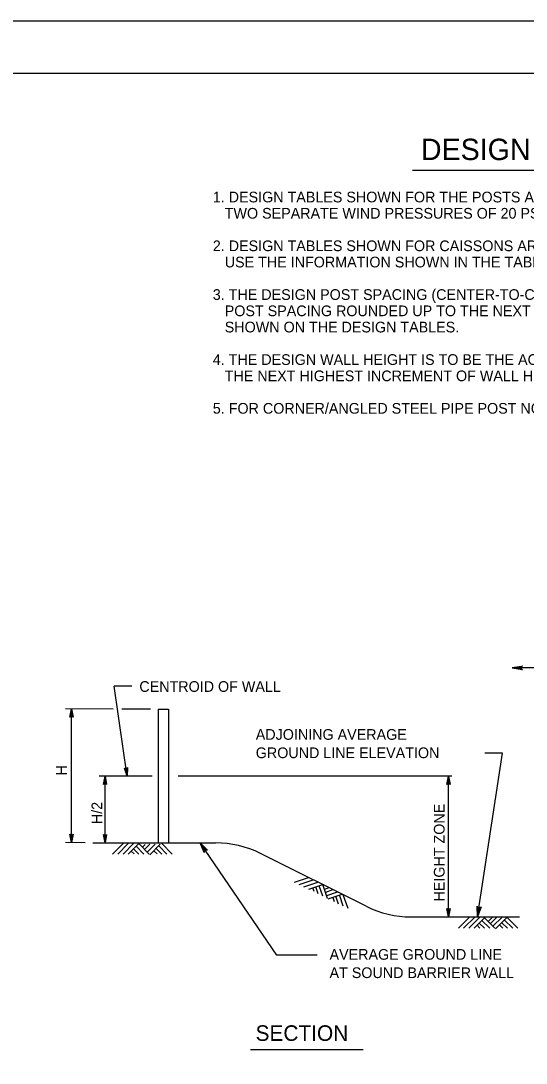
# Model space of a CAD drawing. Extents: x 3475 to 6558, y -3780 to 1166.
# Drawn here: x 4085.3 to 4230.4, y 866.1 to 1165.7 of the extents above; entities that cross this region are included whole.
import ezdxf

# ---------------------------------------------------------------- set-up
doc = ezdxf.new("R2010")
doc.units = 0
for name, color, linetype in [('1', 7, 'Continuous'), ('2', 7, 'Continuous'), ('PLT-BNDY', 7, 'Continuous')]:
    doc.layers.add(name, color=color, linetype=linetype)

msp = doc.modelspace()

# ---------------------------------------------------------------- linework, layer by layer
at = {"layer": '1'}
for p, q in [((4197.8, 1122.78), (4311.11, 1122.78)), ((4363.67, 979.68), (4226.38, 979.68)), ((4117.22, 974.43), (4112.14, 974.43)), ((4115.85, 948.61), (4112.14, 974.43)), ((4111.83, 967.81), (4098.18, 967.92)), ((4099.87, 929.52), (4099.87, 967.92)), ((4122.61, 967.81), (4114.29, 967.81)), ((4124.78, 967.81), (4127.78, 967.81)), ((4124.78, 967.81), (4124.78, 929.41)), ((4127.78, 967.81), (4127.78, 929.41)), ((4216.51, 908.13), (4223.67, 955.16)), ((4223.67, 955.16), (4218.59, 955.16)), ((4123.07, 948.61), (4107.83, 948.61)), ((4109.52, 929.41), (4109.52, 948.61)), ((4209.08, 948.61), (4130.53, 948.61)), ((4208.13, 908.13), (4208.13, 948.61)), ((4103.83, 929.41), (4098.18, 929.52)), ((4105.99, 929.41), (4141.25, 929.41)), ((4111.69, 926.18), (4114.69, 929.18)), ((4113.19, 926.18), (4116.19, 929.18)), ((4114.69, 926.18), (4117.69, 929.18)), ((4116.19, 926.18), (4119.19, 929.18)), ((4122.19, 926.18), (4119.19, 929.18)), ((4121.04, 928.94), (4120.22, 928.12)), ((4122.37, 929), (4120.87, 927.5)), ((4123.87, 929), (4121.62, 926.75)), ((4125.37, 929), (4122.37, 926)), ((4128.78, 926.18), (4125.78, 929.18)), ((4158.88, 897.11), (4136.78, 929.41)), ((4117.87, 926.23), (4117.04, 927.06)), ((4119.19, 926.18), (4117.69, 927.68)), ((4120.69, 926.18), (4118.44, 928.43)), ((4124.46, 926.23), (4123.63, 927.06)), ((4125.78, 926.18), (4124.28, 927.68)), ((4127.28, 926.18), (4125.03, 928.43)), ((4184.53, 911.17), (4154.13, 926.37)), ((4163.95, 918.06), (4167.97, 919.42)), ((4165.3, 917.4), (4169.32, 918.76)), ((4166.64, 916.73), (4170.66, 918.1)), ((4167.99, 916.07), (4172.01, 917.43)), ((4172.02, 914.08), (4171, 917.09)), ((4173.37, 913.41), (4172.01, 917.43)), ((4169.52, 915.38), (4169.14, 916.48)), ((4170.68, 914.74), (4170, 916.75)), ((4173.56, 916.4), (4172.46, 916.03)), ((4174.78, 915.86), (4172.77, 915.18)), ((4176.12, 915.2), (4173.11, 914.18)), ((4177.47, 914.54), (4173.45, 913.18)), ((4176.59, 911.82), (4175.9, 913.83)), ((4177.93, 911.16), (4176.91, 914.17)), ((4179.28, 910.49), (4177.91, 914.51)), ((4175.42, 912.46), (4175.05, 913.56)), ((4197.41, 908.13), (4228.51, 908.13)), ((4210.98, 904.84), (4214.26, 908.13)), ((4212.48, 904.84), (4215.76, 908.13)), ((4213.98, 904.84), (4217.26, 908.13)), ((4215.48, 904.84), (4218.76, 908.13)), ((4221.48, 904.84), (4218.48, 907.84)), ((4220.85, 908.13), (4219.51, 906.78)), ((4222.12, 908.13), (4220.15, 906.16)), ((4223.62, 908.13), (4220.9, 905.41)), ((4225.12, 908.13), (4221.65, 904.66)), ((4228.07, 904.84), (4224.95, 907.96)), ((4217.15, 904.9), (4216.34, 905.71)), ((4218.48, 904.84), (4216.98, 906.34)), ((4219.98, 904.84), (4217.73, 907.09)), ((4223.74, 904.9), (4222.82, 905.83)), ((4225.07, 904.84), (4223.45, 906.46)), ((4226.57, 904.84), (4224.2, 907.21)), ((4170.47, 897.11), (4158.88, 897.11)), ((4151.25, 869.97), (4183.67, 869.97))]:
    msp.add_line(p, q, dxfattribs=at)
for points in [[(4226.38, 979.68), (4229.36, 980.24), (4229.25, 980.16), (4229.13, 980.08), (4229.07, 979.98), (4229.01, 979.88), (4229, 979.78), (4228.98, 979.68), (4229, 979.58), (4229.01, 979.48), (4229.07, 979.38), (4229.13, 979.28), (4229.25, 979.2), (4229.36, 979.12), (4226.38, 979.68), (4229.25, 979.2), (4229.13, 979.28), (4226.38, 979.68), (4229.07, 979.38), (4229.01, 979.48), (4226.38, 979.68), (4229, 979.58), (4228.98, 979.68), (4226.38, 979.68), (4229, 979.78), (4229.01, 979.88), (4226.38, 979.68), (4229.07, 979.98), (4229.13, 980.08), (4226.38, 979.68), (4229.25, 980.16)], [(4099.87, 967.92), (4100.32, 965.53), (4100.26, 965.63), (4100.19, 965.72), (4100.11, 965.77), (4100.03, 965.81), (4099.95, 965.83), (4099.87, 965.84), (4099.79, 965.83), (4099.71, 965.81), (4099.63, 965.77), (4099.55, 965.72), (4099.49, 965.63), (4099.43, 965.53), (4099.87, 967.92), (4099.49, 965.63), (4099.55, 965.72), (4099.87, 967.92), (4099.63, 965.77), (4099.71, 965.81), (4099.87, 967.92), (4099.79, 965.83), (4099.87, 965.84), (4099.87, 967.92), (4099.95, 965.83), (4100.03, 965.81), (4099.87, 967.92), (4100.11, 965.77), (4100.19, 965.72), (4099.87, 967.92), (4100.26, 965.63)], [(4115.85, 948.61), (4115.07, 950.91), (4115.14, 950.83), (4115.22, 950.74), (4115.3, 950.71), (4115.39, 950.67), (4115.47, 950.67), (4115.55, 950.67), (4115.63, 950.69), (4115.71, 950.72), (4115.78, 950.78), (4115.85, 950.83), (4115.9, 950.93), (4115.95, 951.03), (4115.85, 948.61), (4115.9, 950.93), (4115.85, 950.83), (4115.85, 948.61), (4115.78, 950.78), (4115.71, 950.72), (4115.85, 948.61), (4115.63, 950.69), (4115.55, 950.67), (4115.85, 948.61), (4115.47, 950.67), (4115.39, 950.67), (4115.85, 948.61), (4115.3, 950.71), (4115.22, 950.74), (4115.85, 948.61), (4115.14, 950.83)], [(4109.52, 948.61), (4109.97, 946.22), (4109.91, 946.31), (4109.84, 946.41), (4109.76, 946.45), (4109.68, 946.5), (4109.6, 946.52), (4109.52, 946.53), (4109.44, 946.52), (4109.36, 946.5), (4109.28, 946.45), (4109.2, 946.41), (4109.14, 946.31), (4109.08, 946.22), (4109.52, 948.61), (4109.14, 946.31), (4109.2, 946.41), (4109.52, 948.61), (4109.28, 946.45), (4109.36, 946.5), (4109.52, 948.61), (4109.44, 946.52), (4109.52, 946.53), (4109.52, 948.61), (4109.6, 946.52), (4109.68, 946.5), (4109.52, 948.61), (4109.76, 946.45), (4109.84, 946.41), (4109.52, 948.61), (4109.91, 946.31)], [(4208.13, 948.61), (4208.58, 946.22), (4208.52, 946.31), (4208.45, 946.41), (4208.37, 946.45), (4208.29, 946.5), (4208.21, 946.52), (4208.13, 946.53), (4208.05, 946.52), (4207.97, 946.5), (4207.89, 946.45), (4207.81, 946.41), (4207.75, 946.31), (4207.69, 946.22), (4208.13, 948.61), (4207.75, 946.31), (4207.81, 946.41), (4208.13, 948.61), (4207.89, 946.45), (4207.97, 946.5), (4208.13, 948.61), (4208.05, 946.52), (4208.13, 946.53), (4208.13, 948.61), (4208.21, 946.52), (4208.29, 946.5), (4208.13, 948.61), (4208.37, 946.45), (4208.45, 946.41), (4208.13, 948.61), (4208.52, 946.31)], [(4099.87, 929.52), (4099.43, 931.91), (4099.49, 931.81), (4099.55, 931.72), (4099.63, 931.68), (4099.71, 931.63), (4099.79, 931.61), (4099.87, 931.6), (4099.95, 931.61), (4100.03, 931.63), (4100.11, 931.68), (4100.19, 931.72), (4100.26, 931.81), (4100.32, 931.91), (4099.87, 929.52), (4100.26, 931.81), (4100.19, 931.72), (4099.87, 929.52), (4100.11, 931.68), (4100.03, 931.63), (4099.87, 929.52), (4099.95, 931.61), (4099.87, 931.6), (4099.87, 929.52), (4099.79, 931.61), (4099.71, 931.63), (4099.87, 929.52), (4099.63, 931.68), (4099.55, 931.72), (4099.87, 929.52), (4099.49, 931.81)], [(4099.87, 929.52), (4099.43, 931.91), (4099.49, 931.81), (4099.55, 931.72), (4099.63, 931.68), (4099.71, 931.63), (4099.79, 931.61), (4099.87, 931.6), (4099.95, 931.61), (4100.03, 931.63), (4100.11, 931.68), (4100.19, 931.72), (4100.26, 931.81), (4100.32, 931.91), (4099.87, 929.52), (4100.26, 931.81), (4100.19, 931.72), (4099.87, 929.52), (4100.11, 931.68), (4100.03, 931.63), (4099.87, 929.52), (4099.95, 931.61), (4099.87, 931.6), (4099.87, 929.52), (4099.79, 931.61), (4099.71, 931.63), (4099.87, 929.52), (4099.63, 931.68), (4099.55, 931.72), (4099.87, 929.52), (4099.49, 931.81)], [(4109.52, 929.41), (4109.08, 931.79), (4109.14, 931.7), (4109.2, 931.61), (4109.28, 931.56), (4109.36, 931.52), (4109.44, 931.5), (4109.52, 931.49), (4109.6, 931.5), (4109.68, 931.52), (4109.76, 931.56), (4109.84, 931.61), (4109.91, 931.7), (4109.97, 931.79), (4109.52, 929.41), (4109.91, 931.7), (4109.84, 931.61), (4109.52, 929.41), (4109.76, 931.56), (4109.68, 931.52), (4109.52, 929.41), (4109.6, 931.5), (4109.52, 931.49), (4109.52, 929.41), (4109.44, 931.5), (4109.36, 931.52), (4109.52, 929.41), (4109.28, 931.56), (4109.2, 931.61), (4109.52, 929.41), (4109.14, 931.7)], [(4136.78, 929.41), (4138.92, 927.26), (4138.79, 927.31), (4138.66, 927.36), (4138.55, 927.36), (4138.43, 927.35), (4138.34, 927.31), (4138.25, 927.26), (4138.17, 927.19), (4138.1, 927.12), (4138.05, 927.02), (4138, 926.91), (4138, 926.77), (4138, 926.63), (4136.78, 929.41), (4138, 926.77), (4138, 926.91), (4136.78, 929.41), (4138.05, 927.02), (4138.1, 927.12), (4136.78, 929.41), (4138.17, 927.19), (4138.25, 927.26), (4136.78, 929.41), (4138.34, 927.31), (4138.43, 927.35), (4136.78, 929.41), (4138.55, 927.36), (4138.66, 927.36), (4136.78, 929.41), (4138.79, 927.31)], [(4216.51, 908.13), (4216.4, 911.16), (4216.47, 911.03), (4216.53, 910.91), (4216.62, 910.84), (4216.71, 910.76), (4216.8, 910.73), (4216.9, 910.7), (4217, 910.7), (4217.1, 910.7), (4217.21, 910.74), (4217.32, 910.79), (4217.41, 910.89), (4217.51, 910.99), (4216.51, 908.13), (4217.41, 910.89), (4217.32, 910.79), (4216.51, 908.13), (4217.21, 910.74), (4217.1, 910.7), (4216.51, 908.13), (4217, 910.7), (4216.9, 910.7), (4216.51, 908.13), (4216.8, 910.73), (4216.71, 910.76), (4216.51, 908.13), (4216.62, 910.84), (4216.53, 910.91), (4216.51, 908.13), (4216.47, 911.03)], [(4208.13, 908.13), (4207.69, 910.51), (4207.75, 910.42), (4207.81, 910.33), (4207.89, 910.28), (4207.97, 910.23), (4208.05, 910.22), (4208.13, 910.21), (4208.21, 910.22), (4208.29, 910.23), (4208.37, 910.28), (4208.45, 910.33), (4208.52, 910.42), (4208.58, 910.51), (4208.13, 908.13), (4208.52, 910.42), (4208.45, 910.33), (4208.13, 908.13), (4208.37, 910.28), (4208.29, 910.23), (4208.13, 908.13), (4208.21, 910.22), (4208.13, 910.21), (4208.13, 908.13), (4208.05, 910.22), (4207.97, 910.23), (4208.13, 908.13), (4207.89, 910.28), (4207.81, 910.33), (4208.13, 908.13), (4207.75, 910.42)]]:
    msp.add_lwpolyline(points, dxfattribs=at)
for centre, start, end in [((4141.25, 900.61), 63.4349, 90), ((4197.41, 936.93), 243.4349, 270)]:
    msp.add_arc(centre, 28.8, start, end, dxfattribs=at)
at = {"layer": '2'}
msp.add_line((3801.34, 1150.69), (4587.34, 1150.69), dxfattribs=at)
at = {"layer": 'PLT-BNDY'}
msp.add_lwpolyline([(3761.34, 1165.69), (4602.34, 1165.69), (4602.34, 571.69), (3761.34, 571.69)], close=True, dxfattribs=at)

# ---------------------------------------------------------------- texts
at = {"layer": '1'}
for s, height, p in [('DESIGN TABLE NOTES', 6.1441, (4200.21, 1125.67)), ('1. DESIGN TABLES SHOWN FOR THE POSTS AND SPREAD FOOTINGS ARE DEVELOPED FOR', 3.072, (4140.46, 1113.51)), ('   TWO SEPARATE WIND PRESSURES OF 20 PSF AND 28 PSF.', 3.072, (4140.46, 1108.84)), ('2. DESIGN TABLES SHOWN FOR CAISSONS ARE DEVELOPED FOR A 28 PSF.', 3.072, (4140.46, 1099.49)), ('   USE THE INFORMATION SHOWN IN THE TABLES FOR ALL HEIGHT ZONES.', 3.072, (4140.46, 1094.82)), ('3. THE DESIGN POST SPACING (CENTER-TO-CENTER POSTS) IS TO BE THE ACTUAL ', 3.072, (4140.46, 1085.48)), ('   POST SPACING ROUNDED UP TO THE NEXT HIGHEST INCREMENT OF POST SPACING', 3.072, (4140.46, 1080.8)), ('   SHOWN ON THE DESIGN TABLES.', 3.072, (4140.46, 1076.13)), ('4. THE DESIGN WALL HEIGHT IS TO BE THE ACTUAL WALL HEIGHT ROUNDED UP TO', 3.072, (4140.46, 1066.79)), ('   THE NEXT HIGHEST INCREMENT OF WALL HEIGHT SHOWN ON THE DESIGN TABLES.', 3.072, (4140.46, 1062.11)), ('5. FOR CORNER/ANGLED STEEL PIPE POST NOTES REFER TO SHEET 13. ', 3.072, (4140.46, 1052.77)), ('CENTROID OF WALL', 3.072, (4119.36, 972.81)), ('ADJOINING AVERAGE', 3.072, (4152.79, 959.03)), ('GROUND LINE ELEVATION', 3.072, (4152.79, 953.76)), ('AVERAGE GROUND LINE', 3.072, (4173.98, 895.81)), ('AT SOUND BARRIER WALL', 3.072, (4173.98, 890.54)), ('SECTION', 4.477, (4152.74, 872.48))]:
    msp.add_text(s, height=height, dxfattribs=at).set_placement(p)
for s, height, p in [('H', 3.07, (4098.54, 948.77)), ('H/2', 3.072, (4108.71, 934.79)), ('HEIGHT ZONE', 3.072, (4207.01, 912.56))]:
    msp.add_text(s, height=height, rotation=90, dxfattribs=at).set_placement(p)

doc.saveas('drawing.dxf')
